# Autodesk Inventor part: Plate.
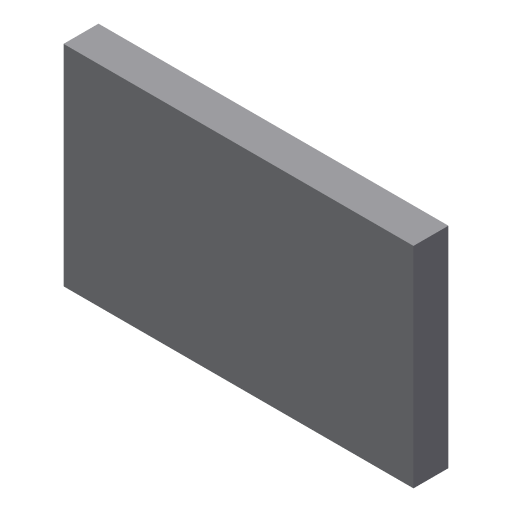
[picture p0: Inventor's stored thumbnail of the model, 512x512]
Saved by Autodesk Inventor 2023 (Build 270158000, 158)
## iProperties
Created: 2010-05
Part Number: Plate.
Document SubType Name: Modeling
Designer: CADSoft
Density: 1 g/cm^3
Material: Generic
Appearance: Default
Author: CADSoft
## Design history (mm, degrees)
sketch "Sketch1"
  geometry: L1 (101.431, -46.382)-(51.431, -46.382); L2 (51.431, -46.382)-(51.431, -76.382); L3 (51.431, -76.382)-(101.431, -76.382); L4 (101.431, -76.382)-(101.431, -46.382); 1 further point
  constraints: 8 end point, 2 parallel, 1 horizontal, 1 perpendicular
  dimensions: "d0" = 30 distance of L3.end L1.start; "d1" = 50 distance of L1.start L1.end
extrude "Extrusion1" new body sketch "Sketch1" distance "d2" = 5; taper "d3" = 0 deg
body "Solid1"
